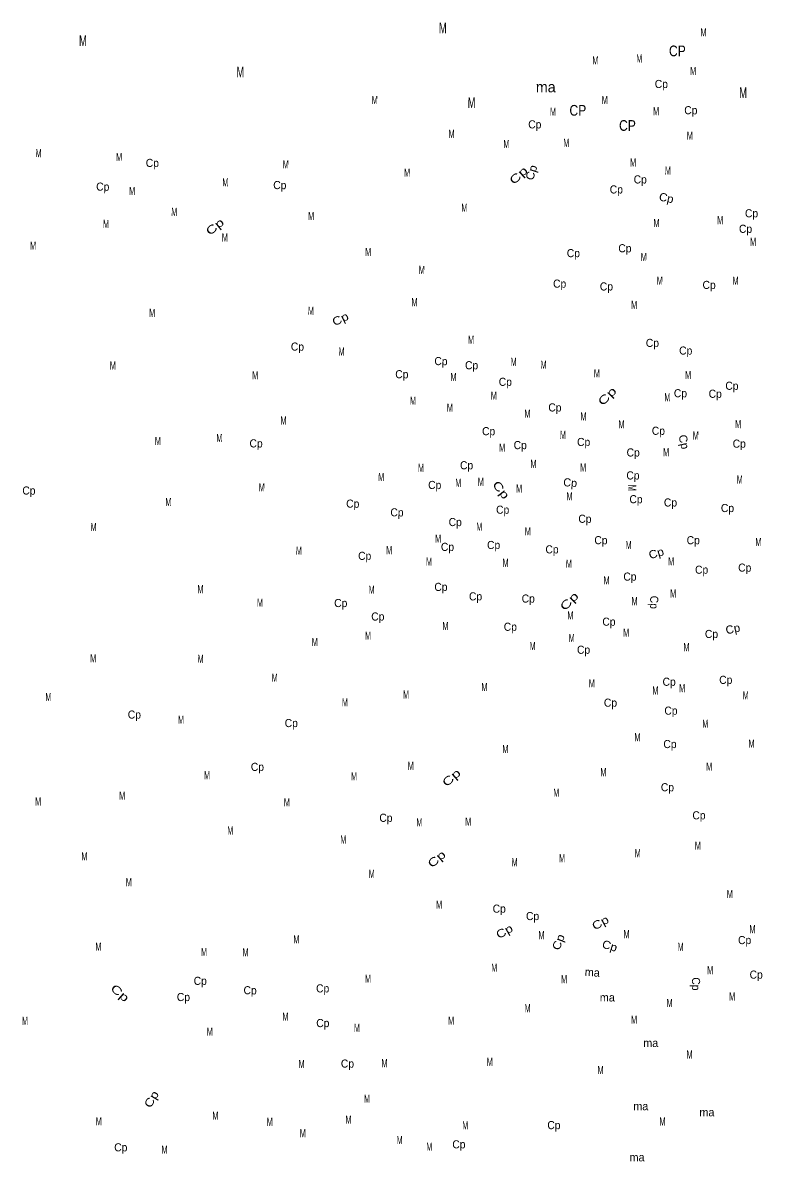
# Model space of a CAD drawing. Extents: x 713577 to 726626, y 7177731 to 7191794.
# Drawn here: x 720172 to 723641, y 7186338 to 7191650 of the extents above; entities that cross this region are included whole.
import ezdxf
from ezdxf.enums import TextEntityAlignment as Align

# ---------------------------------------------------------------- set-up
doc = ezdxf.new("R2010")
doc.units = 0
doc.header["$LTSCALE"] = 15
doc.layers.add('19', color=7, linetype='Continuous')

msp = doc.modelspace()

# ---------------------------------------------------------------- texts
at = {"layer": '19'}
for s, height, rotation, width, p in [('M', 49.99, 359.812, 0.65, (722142.27, 7191599.59)), ('M', 38, 359.799, 0.65, (723364.77, 7191585.32)), ('M', 49.99, 359.812, 0.65, (720454.5, 7191539.66)), ('M', 38, 359.799, 0.65, (723063.82, 7191463.01)), ('M', 49.99, 359.812, 0.65, (721192.83, 7191393.77)), ('M', 38, 359.799, 0.65, (722857.84, 7191453.79)), ('M', 38, 359.799, 0.65, (723316.5, 7191404.21)), ('Cp', 38, 359.799, 0.95, (723167.18, 7191343.35)), ('M', 49.99, 359.812, 0.65, (723550.62, 7191296.12)), ('M', 38, 359.413, 0.65, (721822.91, 7191268.27)), ('M', 49.99, 359.812, 0.65, (722277.28, 7191250.39)), ('M', 38, 359.799, 0.65, (722901.74, 7191268.6)), ('M', 38, 359.799, 0.65, (722658.94, 7191213.59)), ('Cp', 38, 359.799, 0.95, (723305.54, 7191220.42)), ('Cp', 38, 359.799, 0.95, (722573.7, 7191154.22)), ('M', 38, 359.413, 0.65, (722183.25, 7191109.7)), ('M', 38, 359.813, 0.65, (723300.74, 7191101.21)), ('M', 38, 359.799, 0.65, (722440.47, 7191062.56)), ('M', 38, 359.799, 0.65, (722721.48, 7191067.4)), ('M', 38, 359.413, 0.65, (720246.69, 7191019.33)), ('M', 38, 359.413, 0.65, (720624.2, 7191000.79)), ('Cp', 38, 359.413, 0.95, (720780.21, 7190973.43)), ('M', 38, 359.413, 0.65, (721405.64, 7190966.67)), ('M', 38, 359.413, 0.65, (721974.65, 7190928.03)), ('Cp', 38, 42.823, 1.45, (722510.26, 7190920.05)), ('Cp', 38, 72.557, 1.1, (722575.69, 7190941.63)), ('M', 38, 359.799, 0.65, (723034.7, 7190975.5)), ('M', 38, 359.799, 0.65, (723198.04, 7190937.78)), ('M', 38, 359.413, 0.65, (721122.54, 7190882.08)), ('Cp', 38, 359.799, 0.95, (723068.3, 7190896.18)), ('Cp', 38, 359.413, 0.95, (720547.64, 7190862.22)), ('M', 38, 359.413, 0.65, (720685.37, 7190841.75)), ('Cp', 38, 359.413, 0.95, (721377.83, 7190869.59)), ('Cp', 38, 359.799, 0.95, (722956.08, 7190849.28)), ('Cp', 38, 348.266, 1.05, (723186.92, 7190810.1)), ('M', 38, 359.413, 0.65, (720882.99, 7190744.12)), ('M', 38, 359.413, 0.65, (721524.87, 7190724.49)), ('M', 38, 359.799, 0.65, (722243.42, 7190763.41)), ('Cp', 38, 359.799, 0.95, (723590.07, 7190737.47)), ('M', 38, 359.413, 0.65, (720562.78, 7190687.78)), ('Cp', 38, 38.858, 1.4, (721085.44, 7190678.84)), ('M', 38, 359.799, 0.65, (723144.41, 7190691.93)), ('M', 38, 359.799, 0.65, (723443.26, 7190705.28)), ('Cp', 38, 359.799, 0.95, (723561.98, 7190664.83)), ('M', 38, 359.413, 0.65, (721120.25, 7190623.86)), ('M', 38, 359.413, 0.65, (720220.73, 7190586.01)), ('M', 38, 359.413, 0.65, (721792.33, 7190556.29)), ('Cp', 38, 359.799, 0.95, (722996.24, 7190573.63)), ('M', 38, 359.799, 0.65, (723597.45, 7190603.65)), ('Cp', 38, 359.799, 0.95, (722754.58, 7190550.84)), ('M', 38, 359.799, 0.65, (723084.57, 7190532.8)), ('M', 38, 359.413, 0.65, (722043.37, 7190472.22)), ('Cp', 38, 359.799, 0.95, (722690.34, 7190407.83)), ('M', 38, 359.799, 0.65, (723159.57, 7190422.2)), ('Cp', 38, 359.799, 0.95, (723391.14, 7190401.85)), ('M', 38, 359.799, 0.65, (723515.26, 7190421.64)), ('Cp', 38, 359.799, 0.95, (722909.6, 7190394.72)), ('M', 38, 359.413, 0.65, (722009.36, 7190320.87)), ('M', 38, 359.799, 0.65, (723039.85, 7190308.26)), ('M', 38, 359.413, 0.65, (720779.36, 7190270.68)), ('M', 38, 359.413, 0.65, (721523.86, 7190280.69)), ('Cp', 38, 25.98, 1.2, (721670.24, 7190244.05)), ('M', 38, 359.799, 0.65, (722274.79, 7190144.74)), ('Cp', 38, 359.799, 0.95, (723125.24, 7190130.11)), ('Cp', 38, 359.413, 0.95, (721460.61, 7190112.7)), ('M', 38, 359.413, 0.65, (721667.6, 7190089.77)), ('Cp', 38, 359.799, 0.95, (723281.44, 7190094.18)), ('M', 38, 359.413, 0.65, (720594.79, 7190024.2)), ('Cp', 38, 359.413, 0.95, (722133.53, 7190044.77)), ('Cp', 38, 359.413, 0.95, (722277.27, 7190025.31)), ('M', 38, 359.799, 0.65, (722474.55, 7190041.24)), ('M', 38, 359.799, 0.65, (722614.99, 7190028.07)), ('M', 38, 359.413, 0.65, (721262.51, 7189978.55)), ('Cp', 38, 359.413, 0.95, (721950.16, 7189983.22)), ('M', 38, 359.799, 0.65, (722865, 7189987.45)), ('M', 38, 359.799, 0.65, (723292.69, 7189980.03)), ('M', 38, 359.799, 0.65, (722192.62, 7189970.61)), ('Cp', 38, 359.799, 0.95, (722435.5, 7189947.83)), ('Cp', 38, 359.799, 0.95, (723498.11, 7189929.28)), ('M', 38, 359.799, 0.65, (722381.47, 7189883.25)), ('Cp', 38, 45, 1.5, (722926.41, 7189885.71)), ('M', 38, 359.799, 0.65, (723195.28, 7189875.61)), ('Cp', 38, 359.799, 0.95, (723256.75, 7189894.15)), ('Cp', 38, 359.799, 0.95, (723419.86, 7189891.86)), ('M', 38, 359.413, 0.65, (722002.51, 7189859.56)), ('M', 38, 359.413, 0.65, (722175.4, 7189826.32)), ('Cp', 38, 359.799, 0.95, (722668.09, 7189827.77)), ('M', 38, 359.413, 0.65, (721395.11, 7189766.58)), ('M', 38, 359.799, 0.65, (722539.15, 7189798.75)), ('M', 38, 359.799, 0.65, (722801.93, 7189785.49)), ('Cp', 38, 359.799, 0.95, (722357.24, 7189716.46)), ('M', 38, 359.799, 0.65, (722980.33, 7189748.55)), ('Cp', 38, 359.799, 0.95, (723153.27, 7189718.47)), ('M', 38, 359.799, 0.65, (723527.3, 7189749.62)), ('M', 38, 359.413, 0.65, (720806.02, 7189670.66)), ('M', 38, 359.413, 0.65, (721094.4, 7189684.63)), ('Cp', 38, 359.413, 0.95, (721266.65, 7189659.23)), ('M', 38, 359.799, 0.65, (722705.68, 7189699.48)), ('Cp', 38, 359.799, 0.95, (722802.88, 7189665.9)), ('Cp', 38, 282.767, 1.05, (723254.85, 7189681.27)), ('M', 38, 359.799, 0.65, (723328.36, 7189696.18)), ('Cp', 38, 359.799, 0.95, (723532.48, 7189658.06)), ('M', 38, 359.799, 0.65, (722420.71, 7189638.79)), ('Cp', 38, 359.799, 0.95, (722505.39, 7189651.18)), ('Cp', 38, 359.799, 0.95, (723035.04, 7189616.77)), ('M', 38, 359.799, 0.65, (723189.58, 7189617.94)), ('Cp', 38, 359.799, 0.95, (722253.88, 7189556.8)), ('M', 38, 359.799, 0.65, (722567.45, 7189563.24)), ('M', 38, 359.799, 0.65, (722800.4, 7189546.32)), ('M', 38, 359.413, 0.65, (721853.5, 7189501.87)), ('M', 38, 359.413, 0.65, (722039.86, 7189544.84)), ('Cp', 38, 359.799, 0.95, (723033.97, 7189509.17)), ('M', 38, 359.413, 0.65, (721293.12, 7189453.28)), ('Cp', 38, 359.413, 0.95, (722104.3, 7189464.38)), ('M', 38, 359.799, 0.65, (722214.88, 7189474.69)), ('M', 38, 359.799, 0.65, (722320.43, 7189479.12)), ('Cp', 38, 307.794, 1.4, (722400.38, 7189448.83)), ('M', 38, 359.799, 0.65, (722500.22, 7189447.65)), ('M', 38, 270, 0.65, (723011.35, 7189469.59)), ('M', 38, 359.799, 0.65, (723534.61, 7189489.86)), ('Cp', 38, 359.413, 0.95, (720201.28, 7189438.36)), ('M', 38, 359.799, 0.65, (722736.54, 7189411.53)), ('Cp', 38, 359.799, 0.95, (723048.32, 7189397.76)), ('M', 38, 359.413, 0.65, (720855.3, 7189384.74)), ('Cp', 38, 359.413, 0.95, (721719.92, 7189376.94)), ('Cp', 38, 359.413, 0.95, (721927.3, 7189336.01)), ('Cp', 38, 359.799, 0.95, (722423.12, 7189348.55)), ('Cp', 38, 359.799, 0.95, (723210, 7189382.46)), ('Cp', 38, 359.799, 0.95, (723477.26, 7189356.42)), ('Cp', 38, 359.799, 0.95, (722200.52, 7189290.73)), ('Cp', 38, 359.799, 0.95, (722808.81, 7189306.08)), ('M', 38, 359.413, 0.65, (720504.56, 7189267.89)), ('M', 38, 359.799, 0.65, (722313.53, 7189269.09)), ('M', 38, 359.799, 0.65, (722540.98, 7189247.05)), ('M', 38, 359.799, 0.65, (722120.41, 7189213.22)), ('Cp', 38, 359.413, 0.95, (722164.13, 7189174.47)), ('Cp', 38, 359.799, 0.95, (722380.73, 7189183.19)), ('Cp', 38, 359.799, 0.95, (722883.85, 7189205.75)), ('M', 38, 359.799, 0.65, (723013.64, 7189183.03)), ('Cp', 38, 359.799, 0.95, (723316.64, 7189205.61)), ('M', 38, 359.799, 0.65, (723622.21, 7189197.26)), ('M', 38, 359.413, 0.65, (721467.54, 7189156.91)), ('Cp', 38, 359.413, 0.95, (721775.98, 7189132.23)), ('M', 38, 359.413, 0.65, (721890.91, 7189158.93)), ('Cp', 38, 359.799, 0.95, (722654.45, 7189162.7)), ('Cp', 38, 16.64, 1.1, (723148.78, 7189145.6)), ('M', 38, 359.413, 0.65, (722077.34, 7189105.51)), ('M', 38, 359.799, 0.65, (722436.64, 7189099.38)), ('M', 38, 359.799, 0.65, (722733.72, 7189095.6)), ('M', 38, 359.988, 0.65, (723213.4, 7189106.37)), ('Cp', 38, 359.799, 0.95, (723558.18, 7189077.2)), ('M', 38, 359.988, 0.65, (722910.28, 7189017.33)), ('Cp', 38, 359.988, 0.95, (723019.92, 7189035.14)), ('Cp', 38, 359.988, 0.95, (723356.12, 7189067.44)), ('M', 38, 359.99, 0.65, (721005.96, 7188976.34)), ('M', 38, 359.988, 0.65, (721808.56, 7188973.65)), ('Cp', 38, 359.988, 0.95, (722133.53, 7188986.79)), ('M', 38, 359.988, 0.65, (721285.11, 7188913)), ('Cp', 38, 359.988, 0.95, (721663.9, 7188911.26)), ('Cp', 38, 359.988, 0.95, (722296, 7188942.5)), ('Cp', 38, 359.988, 0.95, (722543.02, 7188932.21)), ('Cp', 38, 45, 1.5, (722748.54, 7188925.08)), ('M', 38, 359.988, 0.65, (723041.7, 7188919.88)), ('Cp', 38, 270, 0.95, (723114.82, 7188933.58)), ('M', 38, 359.988, 0.65, (723222.81, 7188955.84)), ('Cp', 38, 359.988, 0.95, (721837.6, 7188848.15)), ('M', 38, 359.988, 0.65, (722154.63, 7188803.83)), ('M', 38, 359.988, 0.65, (722740.83, 7188853.24)), ('Cp', 38, 359.988, 0.95, (722921.46, 7188823.81)), ('M', 38, 359.988, 0.65, (721791.67, 7188758.66)), ('Cp', 38, 359.988, 0.95, (722459.11, 7188800.13)), ('M', 38, 359.988, 0.65, (723002.36, 7188771.94)), ('Cp', 38, 359.988, 0.95, (723402.29, 7188766.24)), ('Cp', 38, 13.13, 1.05, (723506.61, 7188790.82)), ('M', 38, 359.988, 0.65, (721542, 7188728.33)), ('M', 38, 359.988, 0.65, (722563.45, 7188709.95)), ('M', 38, 359.988, 0.65, (722746.75, 7188747.56)), ('M', 38, 359.988, 0.65, (723285.04, 7188704.51)), ('M', 38, 359.99, 0.65, (720503.19, 7188652.16)), ('M', 38, 359.99, 0.65, (721006.89, 7188649.77)), ('Cp', 38, 359.988, 0.95, (722802.55, 7188692.39)), ('M', 38, 359.988, 0.65, (721354.05, 7188561.27)), ('Cp', 38, 359.988, 0.95, (723203.77, 7188542.38)), ('Cp', 38, 359.988, 0.95, (723469.29, 7188551.23)), ('M', 38, 359.988, 0.65, (722337.65, 7188517.26)), ('M', 38, 359.988, 0.65, (722841.15, 7188534.53)), ('M', 38, 359.988, 0.65, (723139.36, 7188501.44)), ('M', 38, 359.988, 0.65, (723264.85, 7188512.31)), ('M', 38, 359.99, 0.65, (720292.67, 7188471.03)), ('M', 38, 359.988, 0.65, (721683.62, 7188445.94)), ('Cp', 38, 359.988, 0.95, (722928.65, 7188444.35)), ('M', 38, 359.988, 0.65, (723562.73, 7188479.22)), ('Cp', 38, 359.99, 0.95, (720696.11, 7188388.56)), ('Cp', 38, 359.988, 0.95, (723212.32, 7188406.97)), ('M', 38, 359.99, 0.65, (720914.81, 7188364.44)), ('Cp', 38, 359.988, 0.95, (721431.95, 7188348.9)), ('M', 38, 359.988, 0.65, (723373.47, 7188345.51)), ('M', 38, 359.988, 0.65, (723055.03, 7188282.44)), ('M', 38, 359.988, 0.65, (722436, 7188226.96)), ('Cp', 38, 359.988, 0.95, (723207.67, 7188250.44)), ('M', 38, 359.988, 0.65, (723590.09, 7188252.34)), ('Cp', 38, 359.99, 0.95, (721273.01, 7188143.7)), ('M', 38, 359.988, 0.65, (721992.14, 7188148.45)), ('M', 38, 359.988, 0.65, (722895.49, 7188118.67)), ('M', 38, 359.988, 0.65, (723391.59, 7188144.72)), ('M', 38, 359.99, 0.65, (721036.82, 7188104.49)), ('M', 38, 359.988, 0.65, (721726.14, 7188099.17)), ('Cp', 38, 41.638, 1.45, (722195.23, 7188097.59)), ('M', 38, 359.99, 0.65, (720638.98, 7188008.23)), ('M', 38, 359.988, 0.65, (722674.53, 7188022.94)), ('Cp', 38, 359.988, 0.95, (723195.73, 7188048)), ('M', 38, 359.99, 0.65, (720244.78, 7187981.25)), ('M', 38, 359.988, 0.65, (721411.39, 7187977.71)), ('Cp', 38, 359.988, 0.95, (721875.7, 7187904.95)), ('Cp', 38, 359.988, 0.95, (723343.66, 7187916.53)), ('M', 38, 359.988, 0.65, (722032.57, 7187884.11)), ('M', 38, 359.988, 0.65, (722261.76, 7187886.71)), ('M', 38, 359.99, 0.65, (721145.96, 7187845.52)), ('M', 38, 359.988, 0.65, (721675.88, 7187802.95)), ('M', 38, 359.988, 0.65, (723338.34, 7187774.19)), ('M', 38, 359.99, 0.65, (720461.76, 7187724.49)), ('Cp', 38, 40.467, 1.4, (722125.68, 7187716.26)), ('M', 38, 359.988, 0.65, (722479.35, 7187697.1)), ('M', 38, 359.988, 0.65, (722701.61, 7187715.54)), ('M', 38, 359.988, 0.65, (723056.3, 7187739.25)), ('M', 38, 359.988, 0.65, (721808.94, 7187642.42)), ('M', 38, 359.99, 0.65, (720669.91, 7187603.48)), ('M', 38, 359.988, 0.65, (722125.28, 7187497.71)), ('Cp', 38, 359.988, 0.95, (722406.95, 7187479.17)), ('Cp', 38, 359.988, 0.95, (722563.48, 7187444.46)), ('Cp', 38, 29.567, 1.25, (722440.6, 7187375.12)), ('Cp', 38, 29.176, 1.25, (722890.45, 7187415.65)), ('M', 38, 359.988, 0.65, (723594.53, 7187382.79)), ('M', 38, 359.988, 0.65, (721455.88, 7187335.65)), ('M', 38, 359.988, 0.65, (722605.14, 7187354.89)), ('Cp', 38, 69.011, 1.15, (722702.02, 7187334.64)), ('M', 38, 359.988, 0.65, (723004.08, 7187359.76)), ('Cp', 38, 359.988, 0.95, (723557.83, 7187331.96)), ('M', 38, 359.99, 0.65, (720527.36, 7187301.35)), ('M', 38, 359.99, 0.65, (721022.82, 7187276.52)), ('M', 38, 359.99, 0.65, (721217.44, 7187274.83)), ('Cp', 38, 342.876, 1.1, (722919.79, 7187305.79)), ('M', 38, 359.988, 0.65, (723257.7, 7187300.26)), ('M', 38, 359.988, 0.65, (722383.84, 7187203.02)), ('M', 38, 359.988, 0.65, (723396.15, 7187190.74)), ('Cp', 38, 359.988, 0.95, (723611.96, 7187170.13)), ('Cp', 38, 359.99, 0.95, (721004.97, 7187140.91)), ('Cp', 38, 359.988, 0.95, (721579.1, 7187105.62)), ('M', 38, 359.988, 0.65, (721791.66, 7187150.69)), ('M', 38, 359.988, 0.65, (722711.11, 7187148.79)), ('Cp', 38, 270, 0.95, (723310.91, 7187145.6)), ('Cp', 38, 318.887, 1.45, (720616.03, 7187088.57)), ('Cp', 38, 359.99, 0.95, (720926.12, 7187065.05)), ('Cp', 38, 358.929, 0.95, (721238.5, 7187096.66)), ('M', 38, 359.988, 0.65, (723499.39, 7187067.38)), ('M', 38, 359.988, 0.65, (722540.01, 7187012.77)), ('M', 38, 359.988, 0.65, (723205.79, 7187037.39)), ('M', 38, 359.99, 0.65, (720183.21, 7186953.29)), ('M', 38, 359.988, 0.65, (721404.61, 7186973.38)), ('Cp', 38, 359.988, 0.95, (721579.73, 7186943.14)), ('M', 38, 359.988, 0.65, (722181.68, 7186954.06)), ('M', 38, 359.988, 0.65, (723039.33, 7186958.83)), ('M', 38, 359.99, 0.65, (721049.79, 7186902.99)), ('M', 38, 359.988, 0.65, (721739.8, 7186920.47)), ('M', 38, 359.988, 0.65, (723299.53, 7186795.63)), ('M', 38, 359.988, 0.65, (721480.19, 7186751.11)), ('Cp', 38, 359.988, 0.95, (721695.27, 7186753.22)), ('M', 38, 359.988, 0.65, (721868.89, 7186754.99)), ('M', 38, 359.988, 0.65, (722362.61, 7186761.16)), ('M', 38, 359.988, 0.65, (722882.08, 7186722.74)), ('Cp', 38, 59.366, 1.25, (720792.4, 7186595.53)), ('M', 38, 359.988, 0.65, (721786.95, 7186589.22)), ('M', 38, 359.99, 0.65, (720529.11, 7186482.95)), ('M', 38, 359.99, 0.65, (721076.11, 7186508.79)), ('M', 38, 359.988, 0.65, (721330.86, 7186480.01)), ('M', 38, 359.988, 0.65, (721700.08, 7186490.83)), ('Cp', 38, 359.988, 0.95, (722663.34, 7186464.93)), ('M', 38, 359.988, 0.65, (723172.65, 7186481.92)), ('M', 38, 359.988, 0.65, (721485.73, 7186427.13)), ('M', 38, 359.988, 0.65, (722247.95, 7186463.96)), ('Cp', 38, 359.99, 0.95, (720632.4, 7186360.82)), ('M', 38, 359.988, 0.65, (721939.82, 7186394.67)), ('M', 38, 359.988, 0.65, (722079.17, 7186363.93)), ('Cp', 38, 359.988, 0.95, (722217.81, 7186374.86)), ('M', 38, 359.99, 0.65, (720837.4, 7186350.28))]:
    msp.add_text(s, height=height, rotation=rotation, dxfattribs=dict(at, width=width)).set_placement(p, align=Align.CENTER)
for s, height, width, p in [('CP', 50, 0.85, (723242.38, 7191492.35)), ('CP', 50, 0.85, (722775.69, 7191213.97)), ('M', 38, 0.65, (723142.46, 7191216.01)), ('CP', 50, 0.85, (723008.31, 7191142.81)), ('M', 38, 0.65, (721969.94, 7188482.54)), ('M', 38, 0.65, (723488.21, 7187547.61))]:
    msp.add_text(s, height=height, dxfattribs=dict(at, width=width)).set_placement(p, align=Align.CENTER)
msp.add_text('ma', height=50, dxfattribs=at).set_placement((722625.15, 7191323.21), align=Align.CENTER)
for s, rotation, p in [('Cp', 354.948, (722738.14, 7189475.53)), ('ma', 355.797, (722842.15, 7187181.14)), ('ma', 359.988, (722913.79, 7187063.28)), ('ma', 359.988, (723117.51, 7186849.9)), ('ma', 359.988, (723070.88, 7186553.67)), ('ma', 359.988, (723380.98, 7186525.21)), ('ma', 359.988, (723053.33, 7186314.25))]:
    msp.add_text(s, height=38, rotation=rotation, dxfattribs=at).set_placement(p, align=Align.CENTER)

doc.saveas('drawing.dxf')
